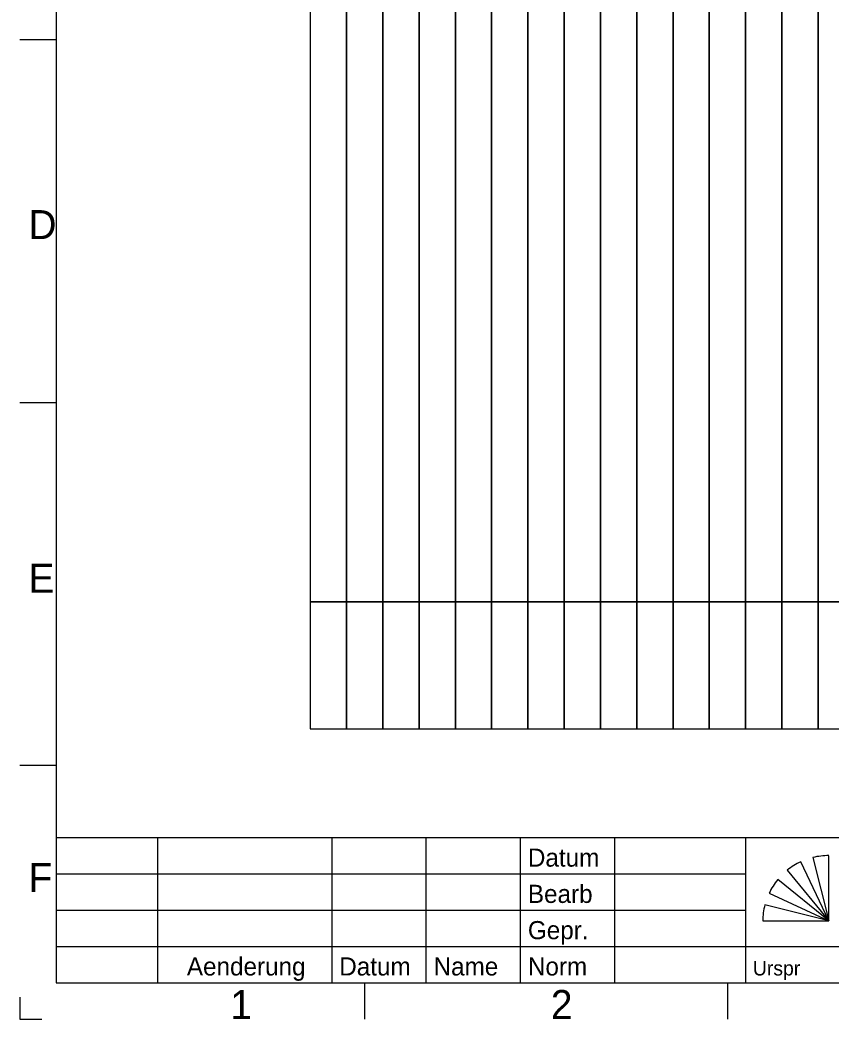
# Model space of a CAD drawing. Extents: x 0 to 395, y 0 to 270.
# Drawn here: x 0 to 111.8, y 0 to 137.7 of the extents above; entities that cross this region are included whole.
import ezdxf

# ---------------------------------------------------------------- set-up
doc = ezdxf.new("R2010")
doc.units = 0
doc.layers.add('90_Plankopf', color=7, linetype='Continuous')

msp = doc.modelspace()

# ---------------------------------------------------------------- linework, layer by layer
at = {"layer": '90_Plankopf'}
for p, q in [((5, 265), (5, 5)), ((0, 135), (5, 135)), ((0, 85), (5, 85)), ((0, 35), (5, 35)), ((5, 25), (390, 25)), ((19, 5), (19, 25)), ((43, 25), (43, 5)), ((56, 5), (56, 25)), ((69, 5), (69, 25)), ((82, 5), (82, 25)), ((100, 25), (100, 5)), ((109.27, 22.26), (111.48, 13.52)), ((111.48, 13.52), (111.48, 22.51)), ((111.48, 13.52), (107.63, 21.68)), ((5, 20), (100, 20)), ((105.74, 20.52), (111.48, 13.52)), ((111.48, 13.52), (104.43, 19.22)), ((103.24, 17.34), (111.48, 13.52)), ((111.48, 13.52), (102.66, 15.72)), ((5, 15), (100, 15)), ((102.36, 13.52), (111.48, 13.52)), ((5, 10), (100, 10)), ((100, 10), (225, 10)), ((5, 5), (390, 5)), ((47.5, 5), (47.5, 0)), ((97.5, 5), (97.5, 0)), ((0, 3), (0, 0)), ((0, 0), (3, 0))]:
    msp.add_line(p, q, dxfattribs=at)
for points in [[(40, 190), (40, 57.5), (45, 57.5), (45, 190)], [(45, 190), (45, 57.5), (50, 57.5), (50, 190)], [(50, 190), (50, 57.5), (55, 57.5), (55, 190)], [(55, 190), (55, 57.5), (60, 57.5), (60, 190)], [(60, 190), (60, 57.5), (65, 57.5), (65, 190)], [(65, 190), (65, 57.5), (70, 57.5), (70, 190)], [(70, 190), (70, 57.5), (75, 57.5), (75, 190)], [(75, 190), (75, 57.5), (80, 57.5), (80, 190)], [(80, 190), (80, 57.5), (85, 57.5), (85, 190)], [(85, 190), (85, 57.5), (90, 57.5), (90, 190)], [(90, 190), (90, 57.5), (95, 57.5), (95, 190)], [(95, 190), (95, 57.5), (100, 57.5), (100, 190)], [(100, 190), (100, 57.5), (105, 57.5), (105, 190)], [(105, 190), (105, 57.5), (110, 57.5), (110, 190)], [(110, 190), (110, 57.5), (115, 57.5), (115, 190)], [(40, 57.5), (40, 40), (45, 40), (45, 57.5)], [(45, 57.5), (45, 40), (50, 40), (50, 57.5)], [(50, 57.5), (50, 40), (55, 40), (55, 57.5)], [(55, 57.5), (55, 40), (60, 40), (60, 57.5)], [(60, 57.5), (60, 40), (65, 40), (65, 57.5)], [(65, 57.5), (65, 40), (70, 40), (70, 57.5)], [(70, 57.5), (70, 40), (75, 40), (75, 57.5)], [(75, 57.5), (75, 40), (80, 40), (80, 57.5)], [(80, 57.5), (80, 40), (85, 40), (85, 57.5)], [(85, 57.5), (85, 40), (90, 40), (90, 57.5)], [(90, 57.5), (90, 40), (95, 40), (95, 57.5)], [(95, 57.5), (95, 40), (100, 40), (100, 57.5)], [(100, 57.5), (100, 40), (105, 40), (105, 57.5)], [(105, 57.5), (105, 40), (110, 40), (110, 57.5)], [(110, 57.5), (110, 40), (115, 40), (115, 57.5)]]:
    msp.add_lwpolyline(points, close=True, dxfattribs=at)
for centre, start, end in [((111.45, 12.99), 89.8053, 103.1895), ((111.66, 13.05), 115.0126, 128.3968), ((111.82, 13.19), 140.7898, 154.174), ((111.89, 13.37), 165.7222, 179.1064)]:
    msp.add_arc(centre, 9.53, start, end, dxfattribs=at)

# ---------------------------------------------------------------- texts
for s, height, p in [('D', 4, (1.17, 107.5)), ('E', 4, (1.17, 58.75)), ('Datum', 2.5, (70, 21)), ('F', 4, (1.17, 17.5)), ('Bearb', 2.5, (70, 16)), ('Gepr.', 2.5, (70, 11)), ('Aenderung', 2.5, (23, 6)), ('Datum', 2.5, (44, 6)), ('Name', 2.5, (57, 6)), ('Norm', 2.5, (70, 6)), ('Urspr', 2, (101, 6)), ('1', 4, (29, 0)), ('2', 4, (73.17, 0))]:
    msp.add_text(s, height=height, dxfattribs=at).set_placement(p)

doc.saveas('drawing.dxf')
